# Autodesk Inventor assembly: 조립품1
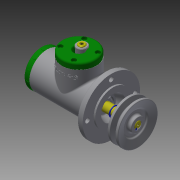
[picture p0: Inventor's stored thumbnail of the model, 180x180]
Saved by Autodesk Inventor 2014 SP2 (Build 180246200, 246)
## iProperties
Created: 2016-08
Part Number: 조립품1
Document SubType Name: Assembly
Designer: 달님반
Author: 달님반
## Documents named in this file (20)
- C:\Users\달님반\Desktop\도진원\조립품1.iam
- C:\Users\달님반\Desktop\도진원\460807V1025\V-벨트풀리.ipt
- C:\Users\달님반\Desktop\도진원\460807V1025\너트 M10.ipt
- C:\Users\달님반\Desktop\도진원\460807V1025\링크.ipt
- C:\Users\달님반\Desktop\도진원\460807V1025\멈춤링 15 x 1.ipt
- C:\Users\달님반\Desktop\도진원\460807V1025\멈춤링 35x1.6.ipt
- C:\Users\달님반\Desktop\도진원\460807V1025\베어링 15 x 35 x 11.ipt
- C:\Users\달님반\Desktop\도진원\460807V1025\부시1.ipt
- C:\Users\달님반\Desktop\도진원\460807V1025\부시2.ipt
- C:\Users\달님반\Desktop\도진원\460807V1025\사이드 커버.ipt
- 사이드 커버.ipt
- C:\Users\달님반\Desktop\도진원\460807V1025\슬라이더.ipt
- C:\Users\달님반\Desktop\도진원\460807V1025\와셔 10x21.ipt
- C:\Users\달님반\Desktop\도진원\460807V1025\클래스터 핀 6 x 24.ipt
- C:\Users\달님반\Desktop\도진원\460807V1025\키 4 x 4 x 18.ipt
- C:\Users\달님반\Desktop\도진원\460807V1025\탑 부시.ipt
- C:\Users\달님반\Desktop\도진원\460807V1025\탑 커버.ipt
- 탑 커버.ipt
- C:\Users\달님반\Desktop\도진원\460807V1025\편심축.ipt
- C:\Users\달님반\Desktop\도진원\도진원.ipt
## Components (1 placed, 1 different names)
1. V-벨트풀리:1
